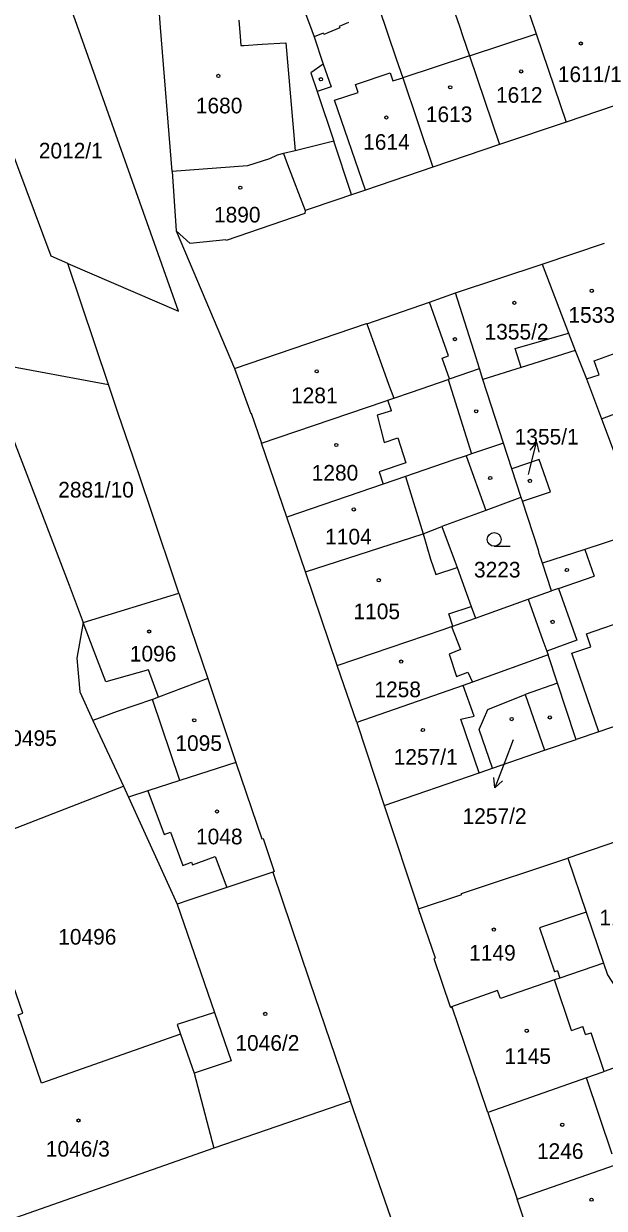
# Model space of a CAD drawing. Extents: x -564952 to -564307, y -1202373 to -1201847.
# Drawn here: x -564475.9 to -564412.8, y -1202215.7 to -1202086.9 of the extents above; entities that cross this region are included whole.
import ezdxf

# ---------------------------------------------------------------- set-up
doc = ezdxf.new("R2010")
doc.units = 0
for name, color, linetype in [('Hranice parcel', 7, 'Continuous'), ('Parcelní čísla', 7, 'Continuous'), ('Pop  PČ popisy', 7, 'Continuous'), ('Vnitřní kresba', 7, 'Continuous'), ('Značky budov', 7, 'Continuous'), ('Značky kultur', 7, 'Continuous')]:
    doc.layers.add(name, color=color, linetype=linetype)

msp = doc.modelspace()

# ---------------------------------------------------------------- linework, layer by layer
at = {"layer": 'Hranice parcel'}
for p, q in [((-564459.79, -1202103), (-564461.05, -1202087.35)), ((-564420.25, -1202088.03), (-564416.99, -1202097.64)), ((-564427.46, -1202090.41), (-564424.23, -1202100.06)), ((-564434.73, -1202092.8), (-564431.46, -1202102.52)), ((-564409.17, -1202094.97), (-564416.99, -1202097.64)), ((-564416.99, -1202097.64), (-564424.23, -1202100.06)), ((-564424.23, -1202100.06), (-564431.46, -1202102.52)), ((-564459.79, -1202103), (-564459.35, -1202109.45)), ((-564459.35, -1202109.45), (-564453, -1202124.38)), ((-564419.59, -1202113.07), (-564412.8, -1202110.76)), ((-564466.68, -1202126.15), (-564471.12, -1202112.99)), ((-564428.98, -1202116.19), (-564419.59, -1202113.07)), ((-564419.59, -1202113.07), (-564416.72, -1202120.54)), ((-564416.72, -1202120.54), (-564415.98, -1202122.44)), ((-564415.98, -1202122.44), (-564414.78, -1202125.53)), ((-564484.26, -1202122.87), (-564466.68, -1202126.15)), ((-564426.01, -1202125.59), (-564426.4, -1202124.41)), ((-564423.77, -1202132.5), (-564426.01, -1202125.59)), ((-564414.78, -1202125.53), (-564413.14, -1202129.85)), ((-564413.14, -1202129.85), (-564406.69, -1202127.47)), ((-564413.14, -1202129.85), (-564411.2, -1202134.99)), ((-564447.33, -1202140.55), (-564450.07, -1202132.51)), ((-564445.31, -1202146.49), (-564447.33, -1202140.55)), ((-564432.52, -1202142.36), (-564430.47, -1202141.57)), ((-564441.84, -1202156.68), (-564445.31, -1202146.49)), ((-564470.96, -1202147.96), (-564469.44, -1202152.01)), ((-564469.44, -1202152.01), (-564459.05, -1202148.8)), ((-564459.05, -1202148.8), (-564455.92, -1202158.1)), ((-564426.82, -1202151.52), (-564421.12, -1202149.47)), ((-564421.12, -1202149.47), (-564419.5, -1202153.95)), ((-564439.72, -1202162.87), (-564441.84, -1202156.68)), ((-564455.92, -1202158.1), (-564452.85, -1202167.22)), ((-564421.42, -1202159.82), (-564419.33, -1202165.89)), ((-564468.39, -1202162.66), (-564465.07, -1202169.78)), ((-564439.72, -1202162.87), (-564436.73, -1202171.88)), ((-564424.96, -1202167.83), (-564426.41, -1202163.62)), ((-564419.33, -1202165.89), (-564415.88, -1202164.71)), ((-564424.96, -1202167.83), (-564419.33, -1202165.89)), ((-564465.07, -1202169.78), (-564464.51, -1202170.97)), ((-564464.51, -1202170.97), (-564459.23, -1202182.61)), ((-564436.73, -1202171.88), (-564433, -1202183.12)), ((-564410.14, -1202175.34), (-564416.78, -1202177.62)), ((-564440.39, -1202204.01), (-564455.26, -1202209.13)), ((-564436.03, -1202216.65), (-564440.39, -1202204.01)), ((-564425.49, -1202205.25), (-564422.31, -1202214.68)), ((-564455.26, -1202209.13), (-564481.73, -1202218.41)), ((-564422.31, -1202214.68), (-564411.73, -1202210.99)), ((-564419.91, -1202221.63), (-564422.31, -1202214.68))]:
    msp.add_line(p, q, dxfattribs=at)
for points in [[(-564471.12, -1202112.99), (-564472.91, -1202112.19), (-564480.33, -1202092.49), (-564473.1, -1202078.61)], [(-564471.12, -1202112.99), (-564459.11, -1202118.17), (-564473.1, -1202078.61)], [(-564461.05, -1202087.35), (-564461.41, -1202082.39), (-564461.59, -1202080.01)], [(-564431.09, -1202079.9), (-564428.53, -1202087.31), (-564428.23, -1202088.2), (-564427.46, -1202090.41)], [(-564438.3, -1202082.34), (-564437.33, -1202085.18), (-564435.44, -1202090.73), (-564434.73, -1202092.8)], [(-564444.84, -1202084.65), (-564445.61, -1202084.93), (-564444.62, -1202087.67), (-564444.37, -1202088.37)], [(-564421.35, -1202084.76), (-564420.86, -1202086.21), (-564420.25, -1202088.03)], [(-564444.37, -1202088.37), (-564443.39, -1202091.32), (-564444.71, -1202092.27)], [(-564444.71, -1202092.27), (-564444.03, -1202094.3), (-564442.23, -1202099.7)], [(-564442.23, -1202099.7), (-564446.4, -1202100.73), (-564447.69, -1202101.05), (-564448.37, -1202101.22)], [(-564440.28, -1202105.54), (-564440.37, -1202105.26), (-564442.23, -1202099.7)], [(-564448.37, -1202101.22), (-564449.2, -1202101.6), (-564451.6, -1202102.39), (-564459.79, -1202103)], [(-564431.46, -1202102.52), (-564438.77, -1202105.01), (-564440.28, -1202105.54)], [(-564440.28, -1202105.54), (-564440.39, -1202105.56), (-564441.79, -1202106.04), (-564445.32, -1202107.24), (-564445.37, -1202107.57), (-564453.91, -1202110.48), (-564453.95, -1202110.41), (-564457.83, -1202110.82), (-564459.35, -1202109.45)], [(-564438.62, -1202119.56), (-564431.81, -1202117.18), (-564428.98, -1202116.19)], [(-564426.4, -1202124.41), (-564426.76, -1202123.25), (-564428.98, -1202116.19)], [(-564453, -1202124.38), (-564438.65, -1202119.52), (-564438.62, -1202119.56)], [(-564415.98, -1202122.44), (-564421.88, -1202124.29), (-564426.01, -1202125.59)], [(-564484.26, -1202122.87), (-564477.85, -1202129.99), (-564475.76, -1202135.44), (-564470.96, -1202147.96)], [(-564453, -1202124.38), (-564451.24, -1202129.27), (-564451.18, -1202129.25), (-564450.07, -1202132.51)], [(-564450.07, -1202132.51), (-564436.76, -1202128), (-564436.34, -1202127.85), (-564435.71, -1202127.63), (-564433.79, -1202126.97), (-564429.79, -1202125.58), (-564429.65, -1202125.53), (-564426.4, -1202124.41)], [(-564459.05, -1202148.8), (-564462.21, -1202139.4), (-564464.03, -1202134.02), (-564465.63, -1202129.27), (-564466.68, -1202126.15)], [(-564423.77, -1202132.5), (-564427.25, -1202133.68), (-564427.85, -1202133.89), (-564429.28, -1202134.37)], [(-564421.85, -1202138.41), (-564422.86, -1202135.31), (-564423.77, -1202132.5)], [(-564429.28, -1202134.37), (-564434.43, -1202136.12), (-564436.85, -1202136.95), (-564447.33, -1202140.55)], [(-564421.85, -1202138.41), (-564421.99, -1202138.46), (-564425.69, -1202139.82), (-564427.28, -1202140.4), (-564430.47, -1202141.57)], [(-564419.97, -1202144.14), (-564421.72, -1202138.83), (-564421.85, -1202138.41)], [(-564430.47, -1202141.57), (-564428.83, -1202146.03), (-564427.28, -1202150.27), (-564426.82, -1202151.52)], [(-564445.31, -1202146.49), (-564433.74, -1202142.77), (-564432.52, -1202142.36)], [(-564408.53, -1202141.96), (-564414.93, -1202144.06), (-564419.54, -1202145.57)], [(-564419.54, -1202145.57), (-564419.89, -1202144.52), (-564419.97, -1202144.14)], [(-564421.12, -1202149.47), (-564420.8, -1202149.35), (-564418.56, -1202148.56), (-564419.54, -1202145.57)], [(-564469.44, -1202152.01), (-564470.14, -1202155.87), (-564469.82, -1202159.55), (-564468.39, -1202162.66)], [(-564429.43, -1202152.44), (-564429.29, -1202152.39), (-564428.29, -1202152.02), (-564426.82, -1202151.52)], [(-564441.84, -1202156.68), (-564430.33, -1202152.75), (-564429.43, -1202152.44)], [(-564419.5, -1202153.95), (-564419.08, -1202155.11), (-564418.94, -1202155.51)], [(-564418.94, -1202155.51), (-564427.16, -1202158.47), (-564428.17, -1202158.84), (-564439.72, -1202162.87)], [(-564415.88, -1202164.71), (-564415.98, -1202164.41), (-564417.92, -1202158.58), (-564418.94, -1202155.51)], [(-564455.92, -1202158.1), (-564461.27, -1202160.11), (-564461.93, -1202160.36), (-564465.74, -1202161.69), (-564468.39, -1202162.66)], [(-564426.41, -1202163.62), (-564425.49, -1202161.44), (-564421.42, -1202159.82)], [(-564401.92, -1202159.96), (-564406.89, -1202161.65), (-564413.42, -1202163.87), (-564415.88, -1202164.71)], [(-564452.85, -1202167.22), (-564458.96, -1202169.19), (-564462.42, -1202170.3), (-564464.51, -1202170.97)], [(-564452.85, -1202167.22), (-564450.05, -1202175.52), (-564449.91, -1202175.48), (-564448.7, -1202179.07), (-564448.84, -1202179.12)], [(-564500.99, -1202168.69), (-564489.98, -1202179.46), (-564465.07, -1202169.78)], [(-564436.73, -1202171.88), (-564426.42, -1202168.33), (-564424.96, -1202167.83)], [(-564433, -1202183.12), (-564428.32, -1202181.55), (-564428.35, -1202181.47), (-564416.78, -1202177.62)], [(-564416.78, -1202177.62), (-564414.79, -1202183.49), (-564412.92, -1202189.01)], [(-564458.87, -1202196.74), (-564473.97, -1202202.06), (-564476.51, -1202194.63), (-564476.01, -1202194.45), (-564477.42, -1202190.36), (-564477.98, -1202190.57), (-564482.07, -1202179.28), (-564486.31, -1202180.92), (-564486.99, -1202179.15), (-564492.02, -1202181.09), (-564491.34, -1202182.86), (-564493.63, -1202183.74), (-564494.46, -1202184.06)], [(-564448.84, -1202179.12), (-564453.85, -1202180.8), (-564457.98, -1202182.19), (-564459.23, -1202182.61)], [(-564448.84, -1202179.12), (-564444.86, -1202190.93), (-564440.39, -1202204.01)], [(-564459.23, -1202182.61), (-564455.17, -1202194.39), (-564459.23, -1202195.69), (-564458.87, -1202196.74)], [(-564429.54, -1202193.79), (-564431.31, -1202188.54), (-564431.18, -1202188.49), (-564433, -1202183.12)], [(-564412.92, -1202189.01), (-564417.66, -1202190.65), (-564418.23, -1202190.85), (-564424.11, -1202192.88), (-564424.43, -1202191.99), (-564429.54, -1202193.79)], [(-564412.92, -1202189.01), (-564412.48, -1202190.3), (-564410.26, -1202193.68), (-564408.45, -1202199.22)], [(-564425.49, -1202205.25), (-564427.31, -1202199.89), (-564429.37, -1202193.82), (-564429.51, -1202193.87), (-564429.54, -1202193.79)], [(-564458.87, -1202196.74), (-564457.4, -1202200.98), (-564455.26, -1202209.13)], [(-564409.94, -1202199.76), (-564412.86, -1202200.81), (-564413, -1202200.86), (-564414.77, -1202201.48), (-564425.49, -1202205.25)]]:
    msp.add_lwpolyline(points, dxfattribs=at)
at = {"layer": 'Pop  PČ popisy'}
for p, q in [((-564420.92, -1202135.32), (-564420.19, -1202132.41)), ((-564420.19, -1202132.41), (-564420.92, -1202133.26)), ((-564420.19, -1202132.41), (-564419.95, -1202133.5)), ((-564421.07, -1202135.93), (-564420.92, -1202135.32)), ((-564422.73, -1202164.75), (-564423.65, -1202167.16)), ((-564423.65, -1202167.16), (-564424.72, -1202169.96)), ((-564424.72, -1202169.96), (-564424.83, -1202168.85)), ((-564424.72, -1202169.96), (-564423.9, -1202169.21))]:
    msp.add_line(p, q, dxfattribs=at)
at = {"layer": 'Vnitřní kresba'}
for p, q in [((-564452.55, -1202086.54), (-564452.4, -1202088.31)), ((-564441.58, -1202087.36), (-564443.3, -1202088.09)), ((-564440.63, -1202086.8), (-564441.64, -1202087.22)), ((-564441.64, -1202087.22), (-564441.58, -1202087.36)), ((-564452.4, -1202088.31), (-564452.31, -1202089.3)), ((-564452.01, -1202089.28), (-564449.99, -1202089.15)), ((-564449.99, -1202089.15), (-564447.42, -1202088.99)), ((-564447.42, -1202088.99), (-564446.4, -1202100.73)), ((-564443.36, -1202087.94), (-564444.37, -1202088.37)), ((-564443.3, -1202088.09), (-564443.36, -1202087.94)), ((-564427.46, -1202090.41), (-564420.25, -1202088.03)), ((-564452.31, -1202089.3), (-564452.01, -1202089.28)), ((-564427.46, -1202090.41), (-564434.73, -1202092.8)), ((-564443.39, -1202091.32), (-564442.51, -1202093.79)), ((-564439.85, -1202093.54), (-564436.09, -1202092.27)), ((-564436.09, -1202092.27), (-564435.8, -1202093.15)), ((-564435.8, -1202093.15), (-564434.73, -1202092.8)), ((-564442.51, -1202093.79), (-564444.03, -1202094.3)), ((-564439.57, -1202094.4), (-564439.85, -1202093.54)), ((-564442.13, -1202095.25), (-564439.57, -1202094.4)), ((-564438.77, -1202105.01), (-564442.13, -1202095.25)), ((-564447.69, -1202101.05), (-564447.25, -1202102.21)), ((-564447.25, -1202102.21), (-564445.32, -1202107.24)), ((-564429.76, -1202123.03), (-564431.81, -1202117.18)), ((-564438.62, -1202119.56), (-564438.51, -1202119.85)), ((-564438.51, -1202119.85), (-564436.85, -1202124.46)), ((-564422.52, -1202122.22), (-564416.72, -1202120.54)), ((-564421.88, -1202124.29), (-564422.52, -1202122.22)), ((-564413.93, -1202123.58), (-564411.16, -1202122.55)), ((-564430.44, -1202123.27), (-564429.76, -1202123.03)), ((-564429.65, -1202125.53), (-564430.44, -1202123.27)), ((-564413.38, -1202125.07), (-564413.93, -1202123.58)), ((-564436.85, -1202124.46), (-564436.26, -1202126.1)), ((-564414.78, -1202125.53), (-564413.38, -1202125.07)), ((-564436.26, -1202126.1), (-564435.71, -1202127.63)), ((-564429.79, -1202125.58), (-564427.25, -1202133.68)), ((-564435.96, -1202129), (-564437.49, -1202129.47)), ((-564435.96, -1202129), (-564436.34, -1202127.85)), ((-564437.49, -1202129.47), (-564436.73, -1202132.45)), ((-564436.73, -1202132.45), (-564435.27, -1202131.92)), ((-564435.27, -1202131.92), (-564434.38, -1202134.65)), ((-564427.85, -1202133.89), (-564425.69, -1202139.82)), ((-564434.38, -1202134.65), (-564437.29, -1202135.61)), ((-564419.89, -1202134.29), (-564422.86, -1202135.31)), ((-564418.69, -1202137.79), (-564419.89, -1202134.29)), ((-564437.29, -1202135.61), (-564436.85, -1202136.95)), ((-564434.43, -1202136.12), (-564432.52, -1202142.36)), ((-564421.72, -1202138.83), (-564418.69, -1202137.79)), ((-564432.52, -1202142.36), (-564431.72, -1202145.12)), ((-564414.93, -1202144.06), (-564413.93, -1202146.97)), ((-564431.72, -1202145.12), (-564431.13, -1202146.78)), ((-564431.13, -1202146.78), (-564428.83, -1202146.03)), ((-564417.81, -1202148.3), (-564413.93, -1202146.97)), ((-564417.81, -1202148.3), (-564418.56, -1202148.56)), ((-564417.81, -1202148.3), (-564415.81, -1202153.93)), ((-564429.73, -1202151.07), (-564427.28, -1202150.27)), ((-564414.78, -1202153.23), (-564405.48, -1202150.04)), ((-564468.27, -1202155.14), (-564469.44, -1202152.01)), ((-564429.29, -1202152.39), (-564429.73, -1202151.07)), ((-564429.43, -1202152.44), (-564428.45, -1202154.94)), ((-564414.3, -1202154.63), (-564414.78, -1202153.23)), ((-564415.81, -1202153.93), (-564419.08, -1202155.11)), ((-564416.35, -1202155.33), (-564414.3, -1202154.63)), ((-564466.98, -1202158.44), (-564468.27, -1202155.14)), ((-564428.45, -1202154.94), (-564429.7, -1202155.43)), ((-564429.7, -1202155.43), (-564428.88, -1202157.86)), ((-564413.42, -1202163.87), (-564416.35, -1202155.33)), ((-564462.37, -1202157.16), (-564466.98, -1202158.44)), ((-564461.27, -1202160.11), (-564462.37, -1202157.16)), ((-564428.88, -1202157.86), (-564427.66, -1202157.39)), ((-564427.66, -1202157.39), (-564427.16, -1202158.47)), ((-564417.92, -1202158.58), (-564421.42, -1202159.82)), ((-564426.96, -1202162.19), (-564428.17, -1202158.84)), ((-564458.96, -1202169.19), (-564461.93, -1202160.36)), ((-564428.43, -1202162.5), (-564426.96, -1202162.19)), ((-564426.42, -1202168.33), (-564428.43, -1202162.5)), ((-564462.42, -1202170.3), (-564460.65, -1202175.03)), ((-564460.65, -1202175.03), (-564459.97, -1202174.78)), ((-564459.97, -1202174.78), (-564458.62, -1202178.41)), ((-564457.58, -1202178.34), (-564455.1, -1202177.42)), ((-564455.1, -1202177.42), (-564453.85, -1202180.8)), ((-564458.62, -1202178.41), (-564457.68, -1202178.06)), ((-564457.68, -1202178.06), (-564457.58, -1202178.34)), ((-564414.79, -1202183.49), (-564419.87, -1202185.18)), ((-564419.87, -1202185.18), (-564418.25, -1202189.96)), ((-564417.93, -1202189.86), (-564418.25, -1202189.96)), ((-564416.41, -1202196.33), (-564418.23, -1202190.85)), ((-564417.93, -1202189.86), (-564417.66, -1202190.65)), ((-564455.17, -1202194.39), (-564453.36, -1202199.65)), ((-564416.41, -1202196.33), (-564415.18, -1202195.92)), ((-564414.89, -1202196.79), (-564415.18, -1202195.92)), ((-564414.89, -1202196.79), (-564414.26, -1202196.59)), ((-564412.86, -1202200.81), (-564414.26, -1202196.59)), ((-564453.36, -1202199.65), (-564457.4, -1202200.98)), ((-564411.97, -1202209.79), (-564414.77, -1202201.48))]:
    msp.add_line(p, q, dxfattribs=at)
at = {"layer": 'Značky budov'}
for centre in [(-564415.38, -1202089.08), (-564454.76, -1202092.6), (-564443.62, -1202092.96), (-564421.86, -1202092.11), (-564429.57, -1202093.84), (-564436.51, -1202097.12), (-564452.38, -1202104.75), (-564414.19, -1202115.95), (-564422.6, -1202117.26), (-564429.06, -1202121.21), (-564444.08, -1202124.71), (-564426.75, -1202129.05), (-564441.95, -1202132.71), (-564425.22, -1202136.3), (-564420.91, -1202136.61), (-564440.05, -1202139.71), (-564416.89, -1202146.3), (-564437.33, -1202147.41), (-564418.45, -1202151.94), (-564462.28, -1202152.98), (-564434.9, -1202156.25), (-564457.38, -1202162.63), (-564422.89, -1202162.5), (-564418.75, -1202162.32), (-564432.54, -1202163.69), (-564454.91, -1202172.54), (-564424.83, -1202185.37), (-564449.67, -1202194.54), (-564421.25, -1202196.37), (-564469.96, -1202206.12), (-564417.4, -1202206.59), (-564414.22, -1202214.73)]:
    msp.add_circle(centre, 0.175, dxfattribs=at)
at = {"layer": 'Značky kultur'}
msp.add_line((-564424.79, -1202143.72), (-564423.04, -1202143.72), dxfattribs=at)
msp.add_circle((-564424.79, -1202142.97), 0.75, dxfattribs=at)

# ---------------------------------------------------------------- texts
at = {"layer": 'Parcelní čísla'}
for s, p in [('1611/1', (-564417.88, -1202093.27)), ('1612', (-564424.6, -1202095.52)), ('1680', (-564457.21, -1202096.67)), ('1613', (-564432.22, -1202097.62)), ('1614', (-564439.03, -1202100.63)), ('2012/1', (-564474.27, -1202101.57)), ('1890', (-564455.24, -1202108.53)), ('1533', (-564416.73, -1202119.43)), ('1355/2', (-564425.84, -1202121.25)), ('1281', (-564446.87, -1202128.17)), ('1355/1', (-564422.57, -1202132.66)), ('1280', (-564444.62, -1202136.58)), ('2881/10', (-564472.16, -1202138.42)), ('1104', (-564443.16, -1202143.52)), ('3223', (-564426.99, -1202147.11)), ('1105', (-564440.08, -1202151.64)), ('1096', (-564464.38, -1202156.24)), ('1258', (-564437.81, -1202160.12)), ('10495', (-564478.64, -1202165.42)), ('1095', (-564459.43, -1202165.96)), ('1257/1', (-564435.71, -1202167.46)), ('1257/2', (-564428.23, -1202173.89)), ('1048', (-564457.19, -1202176.11)), ('1147', (-564413.37, -1202184.92)), ('10496', (-564472.16, -1202187.01)), ('1149', (-564427.51, -1202188.75)), ('1046/2', (-564452.91, -1202198.54)), ('1145', (-564423.68, -1202199.97)), ('1046/3', (-564473.51, -1202210.05)), ('1246', (-564420.15, -1202210.3))]:
    msp.add_text(s, height=1.7, dxfattribs=at).set_placement(p)

doc.saveas('drawing.dxf')
